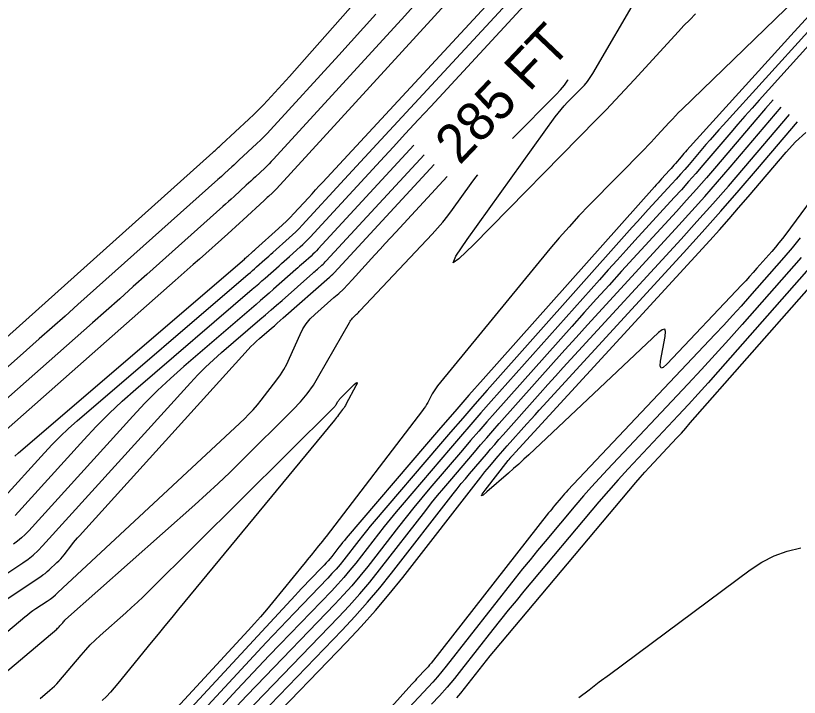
# Model space of a CAD drawing. Extents: x 1768942 to 1774819, y 723037 to 732099.
# Drawn here: x 1771312.2 to 1771433.6, y 725000 to 725105.7 of the extents above; entities that cross this region are included whole.
import ezdxf

# ---------------------------------------------------------------- set-up
doc = ezdxf.new("R2010")
doc.units = 0
doc.layers.add('R_Contour Annot', color=7, linetype='Continuous')
doc.layers.add('R_Contours', color=7, linetype='Continuous')

msp = doc.modelspace()

# ---------------------------------------------------------------- linework, layer by layer
at = {"layer": 'R_Contours'}
for points in [[(1771309.19, 725054.48), (1771342.73, 725084.45), (1771342.84, 725084.55), (1771342.95, 725084.65), (1771343.07, 725084.75), (1771343.18, 725084.86), (1771343.63, 725085.27), (1771343.74, 725085.37), (1771343.85, 725085.47), (1771343.96, 725085.58), (1771344.07, 725085.68), (1771348.33, 725089.65), (1771349.07, 725090.35), (1771349.8, 725091.07), (1771350.51, 725091.8), (1771351.21, 725092.54), (1771354.59, 725096.24), (1771355.38, 725097.11), (1771356.17, 725097.99), (1771356.95, 725098.86), (1771357.73, 725099.74), (1771383.9, 725129.4)], [(1771312.08, 725037.43), (1771312.61, 725037.91), (1771347.62, 725067.96), (1771347.76, 725068.09), (1771347.9, 725068.21), (1771348.05, 725068.33), (1771348.19, 725068.46), (1771348.75, 725068.96), (1771348.9, 725069.09), (1771349.04, 725069.21), (1771349.18, 725069.34), (1771349.32, 725069.46), (1771352.91, 725072.68), (1771353.53, 725073.24), (1771354.12, 725073.81), (1771354.71, 725074.4), (1771355.28, 725075.01), (1771357.53, 725077.45), (1771358.1, 725078.06), (1771358.66, 725078.67), (1771359.22, 725079.28), (1771359.79, 725079.89), (1771394.72, 725117.69)], [(1771384.3, 725113.52), (1771352.58, 725078.84), (1771352.44, 725078.68), (1771352.28, 725078.52), (1771352.13, 725078.37), (1771351.97, 725078.22), (1771351.33, 725077.62), (1771351.17, 725077.47), (1771351.01, 725077.33), (1771350.85, 725077.18), (1771350.69, 725077.03), (1771347.44, 725074.05), (1771346.85, 725073.51), (1771346.25, 725072.96), (1771345.65, 725072.42), (1771345.05, 725071.88), (1771340.64, 725067.94), (1771339.7, 725067.11), (1771338.76, 725066.27), (1771337.82, 725065.44), (1771336.88, 725064.61), (1771306.68, 725037.99)], [(1771309.99, 725030.58), (1771316.65, 725037.92), (1771317.86, 725039.22), (1771319.1, 725040.47), (1771320.39, 725041.68), (1771321.72, 725042.86), (1771348.22, 725065.62), (1771348.54, 725065.89), (1771348.86, 725066.17), (1771349.19, 725066.45), (1771349.5, 725066.73), (1771350.78, 725067.86), (1771351.1, 725068.14), (1771351.42, 725068.42), (1771351.74, 725068.71), (1771352.05, 725068.99), (1771354.56, 725071.23), (1771355.08, 725071.71), (1771355.59, 725072.19), (1771356.08, 725072.69), (1771356.56, 725073.2), (1771363.12, 725080.32), (1771364.38, 725081.67), (1771365.63, 725083.03), (1771366.88, 725084.39), (1771368.14, 725085.75), (1771394.76, 725114.55)], [(1771312.11, 725028.22), (1771322.73, 725039.93), (1771324.66, 725042), (1771326.65, 725044), (1771328.7, 725045.94), (1771330.82, 725047.81), (1771348.83, 725063.27), (1771349.33, 725063.7), (1771349.83, 725064.13), (1771350.33, 725064.57), (1771350.82, 725065.01), (1771352.98, 725066.91), (1771353.39, 725067.27), (1771353.8, 725067.64), (1771354.21, 725068), (1771354.62, 725068.37), (1771356.25, 725069.83), (1771356.65, 725070.2), (1771357.05, 725070.58), (1771357.43, 725070.96), (1771357.81, 725071.36), (1771368.72, 725083.18), (1771370.66, 725085.29), (1771372.6, 725087.39), (1771374.54, 725089.5), (1771376.49, 725091.6), (1771394.8, 725111.41)], [(1771434.68, 725109.88), (1771415.38, 725091.12), (1771414.89, 725090.64), (1771414.4, 725090.14), (1771413.92, 725089.64), (1771413.44, 725089.13), (1771411.56, 725087.07), (1771411.09, 725086.56), (1771410.61, 725086.06), (1771410.13, 725085.55), (1771409.64, 725085.05), (1771401.03, 725076.29), (1771399.45, 725074.64), (1771397.91, 725072.96), (1771396.4, 725071.25), (1771394.94, 725069.51), (1771377.55, 725048.31), (1771377.32, 725048.02), (1771377.11, 725047.71), (1771376.91, 725047.4), (1771376.73, 725047.07), (1771376.02, 725045.75), (1771375.84, 725045.42), (1771375.65, 725045.1), (1771375.44, 725044.79), (1771375.22, 725044.49), (1771360.27, 725024.97), (1771359.99, 725024.6), (1771359.7, 725024.24), (1771359.41, 725023.87), (1771359.12, 725023.51), (1771357.94, 725022.08), (1771357.64, 725021.72), (1771357.35, 725021.36), (1771357.06, 725021.01), (1771356.76, 725020.65), (1771351.96, 725014.72), (1771351.05, 725013.62), (1771350.12, 725012.54), (1771349.18, 725011.47), (1771348.22, 725010.41), (1771332.79, 724993.74)], [(1771417.49, 725105.93), (1771416.6, 725105.03), (1771415.72, 725104.12), (1771414.86, 725103.19), (1771408, 725095.71), (1771406.57, 725094.16), (1771405.12, 725092.62), (1771403.66, 725091.09), (1771402.18, 725089.58), (1771383.09, 725070.15), (1771380.85, 725067.98), (1771379.94, 725067.39), (1771380.36, 725068.39), (1771382.12, 725070.97), (1771395.76, 725089.97), (1771396.21, 725090.57), (1771396.68, 725091.14), (1771397.17, 725091.7), (1771397.69, 725092.24), (1771399.8, 725094.37), (1771400.31, 725094.91), (1771400.78, 725095.48), (1771401.21, 725096.09), (1771401.6, 725096.72), (1771408.8, 725109.07)], [(1771374.25, 725107.61), (1771372.46, 725105.65), (1771352.13, 725083.41), (1771351.79, 725083.05), (1771351.46, 725082.7), (1771351.11, 725082.36), (1771350.76, 725082.03), (1771349.33, 725080.7), (1771348.98, 725080.37), (1771348.62, 725080.04), (1771348.26, 725079.71), (1771347.91, 725079.38), (1771346.02, 725077.65), (1771345.59, 725077.25), (1771345.15, 725076.86), (1771344.71, 725076.46), (1771344.28, 725076.07), (1771332.52, 725065.57), (1771330.41, 725063.69), (1771328.3, 725061.81), (1771326.18, 725059.94), (1771324.07, 725058.07), (1771307.03, 725043.06)], [(1771435.66, 725106.31), (1771432.81, 725103.16), (1771416.16, 725084.81), (1771415.93, 725084.56), (1771415.71, 725084.3), (1771415.49, 725084.05), (1771415.27, 725083.79), (1771414.39, 725082.76), (1771414.17, 725082.5), (1771413.94, 725082.25), (1771413.72, 725081.99), (1771413.49, 725081.74), (1771412.26, 725080.4), (1771411.98, 725080.09), (1771411.7, 725079.78), (1771411.42, 725079.47), (1771411.14, 725079.16), (1771384.62, 725049.36), (1771382.4, 725046.86), (1771380.2, 725044.35), (1771378.01, 725041.82), (1771375.84, 725039.28), (1771363.4, 725024.7), (1771363.11, 725024.35), (1771362.83, 725024.01), (1771362.54, 725023.66), (1771362.27, 725023.31), (1771361.17, 725021.89), (1771360.89, 725021.54), (1771360.6, 725021.2), (1771360.3, 725020.87), (1771360, 725020.54), (1771357.51, 725017.97), (1771357, 725017.43), (1771356.48, 725016.89), (1771355.97, 725016.35), (1771355.46, 725015.8), (1771333.53, 724992.1)], [(1771368, 725105.92), (1771366.09, 725103.79), (1771364.17, 725101.66), (1771362.24, 725099.54), (1771351.67, 725087.98), (1771351.15, 725087.43), (1771350.63, 725086.89), (1771350.09, 725086.36), (1771349.55, 725085.84), (1771346.78, 725083.26), (1771346.51, 725083.01), (1771346.24, 725082.76), (1771345.96, 725082.51), (1771345.69, 725082.26), (1771344.6, 725081.25), (1771344.33, 725081), (1771344.05, 725080.75), (1771343.78, 725080.51), (1771343.5, 725080.26), (1771321.82, 725060.89), (1771319.83, 725059.12), (1771317.84, 725057.35), (1771315.84, 725055.58), (1771313.85, 725053.82), (1771305.85, 725046.77)], [(1771434.9, 725103.18), (1771421.77, 725088.7), (1771421.1, 725087.95), (1771420.43, 725087.2), (1771419.77, 725086.44), (1771419.11, 725085.68), (1771416.51, 725082.62), (1771415.85, 725081.85), (1771415.19, 725081.1), (1771414.52, 725080.35), (1771413.84, 725079.6), (1771410.19, 725075.62), (1771409.36, 725074.7), (1771408.53, 725073.79), (1771407.7, 725072.87), (1771406.87, 725071.95), (1771385.24, 725047.64), (1771383.34, 725045.49), (1771381.44, 725043.32), (1771379.56, 725041.15), (1771377.69, 725038.97), (1771367.72, 725027.28), (1771367.11, 725026.56), (1771366.51, 725025.83), (1771365.92, 725025.09), (1771365.34, 725024.35), (1771363.02, 725021.37), (1771362.43, 725020.64), (1771361.82, 725019.92), (1771361.19, 725019.21), (1771360.55, 725018.52), (1771355.31, 725013.1), (1771354.22, 725011.96), (1771353.14, 725010.82), (1771352.06, 725009.68), (1771350.99, 725008.53), (1771334.28, 724990.46)], [(1771436.99, 725103.19), (1771427.37, 725092.59), (1771426.26, 725091.35), (1771425.15, 725090.1), (1771424.05, 725088.84), (1771422.96, 725087.57), (1771418.63, 725082.48), (1771417.54, 725081.21), (1771416.44, 725079.95), (1771415.32, 725078.7), (1771414.2, 725077.47), (1771408.12, 725070.83), (1771406.74, 725069.32), (1771405.35, 725067.79), (1771403.98, 725066.26), (1771402.61, 725064.73), (1771385.86, 725045.91), (1771384.27, 725044.11), (1771382.68, 725042.3), (1771381.11, 725040.48), (1771379.54, 725038.66), (1771372.04, 725029.86), (1771371.11, 725028.76), (1771370.2, 725027.65), (1771369.29, 725026.53), (1771368.4, 725025.4), (1771364.87, 725020.85), (1771363.97, 725019.73), (1771363.04, 725018.63), (1771362.08, 725017.56), (1771361.1, 725016.51), (1771353.11, 725008.23), (1771351.45, 725006.5), (1771349.8, 725004.76), (1771348.16, 725003.01), (1771346.52, 725001.26), (1771335.02, 724988.82)], [(1771450.24, 725097.21), (1771431.49, 725071.82), (1771430.97, 725071.13), (1771430.43, 725070.45), (1771429.88, 725069.78), (1771429.32, 725069.13), (1771427.03, 725066.53), (1771426.46, 725065.88), (1771425.88, 725065.24), (1771425.29, 725064.6), (1771424.7, 725063.97), (1771413.07, 725051.65), (1771412.51, 725051.15), (1771412.16, 725051.07), (1771412.02, 725051.4), (1771412.09, 725052.15), (1771412.81, 725055.97), (1771412.88, 725056.72), (1771412.73, 725057.07), (1771412.35, 725057.01), (1771411.76, 725056.55), (1771391.67, 725037.64), (1771390.89, 725036.92), (1771390.11, 725036.19), (1771389.31, 725035.48), (1771388.51, 725034.77), (1771385.18, 725031.86), (1771384.6, 725031.38), (1771384.36, 725031.27), (1771384.46, 725031.51), (1771384.9, 725032.12), (1771388.49, 725036.72), (1771388.52, 725036.77), (1771388.56, 725036.82), (1771388.6, 725036.86), (1771388.64, 725036.91), (1771388.8, 725037.1), (1771388.84, 725037.15), (1771388.88, 725037.19), (1771388.92, 725037.24), (1771388.96, 725037.29), (1771389.32, 725037.69), (1771389.39, 725037.77), (1771389.47, 725037.85), (1771389.54, 725037.93), (1771389.61, 725038.01), (1771419.7, 725070.84), (1771421.21, 725072.5), (1771422.7, 725074.18), (1771424.18, 725075.87), (1771425.64, 725077.57), (1771431.56, 725084.51), (1771433.02, 725086.1), (1771434.6, 725087.55)], [(1771389.13, 725086.64), (1771395.93, 725093.47), (1771396.59, 725094.17), (1771397.19, 725094.91), (1771397.75, 725095.69), (1771397.78, 725095.74)], [(1771429.53, 725092.6), (1771428.36, 725091.26), (1771426.87, 725089.52), (1771420.74, 725082.33), (1771419.22, 725080.56), (1771417.68, 725078.8), (1771416.13, 725077.06), (1771414.55, 725075.33), (1771406.05, 725066.05), (1771404.11, 725063.93), (1771402.18, 725061.8), (1771400.26, 725059.66), (1771398.34, 725057.52), (1771386.48, 725044.19), (1771385.2, 725042.74), (1771383.92, 725041.28), (1771382.65, 725039.82), (1771381.39, 725038.35), (1771376.36, 725032.45), (1771375.12, 725030.97), (1771373.88, 725029.47), (1771372.67, 725027.97), (1771371.47, 725026.45), (1771366.72, 725020.33), (1771365.51, 725018.82), (1771364.26, 725017.34), (1771362.97, 725015.9), (1771361.65, 725014.49), (1771349.48, 725001.87), (1771347.96, 725000.29), (1771346.45, 724998.7)], [(1771340.45, 724987.33), (1771362.75, 725010.45), (1771364.75, 725012.59), (1771366.7, 725014.77), (1771368.59, 725017.01), (1771370.41, 725019.29), (1771379.98, 725031.58), (1771380.6, 725032.37), (1771381.22, 725033.15), (1771381.86, 725033.92), (1771382.5, 725034.68), (1771385.1, 725037.72), (1771385.75, 725038.48), (1771386.4, 725039.24), (1771387.06, 725039.99), (1771387.72, 725040.74), (1771393.46, 725047.18), (1771394.64, 725048.51), (1771395.83, 725049.82), (1771397.02, 725051.13), (1771398.21, 725052.44), (1771415.26, 725071.05), (1771417.73, 725073.77), (1771420.17, 725076.51), (1771422.59, 725079.27), (1771424.98, 725082.05), (1771432.05, 725090.36)], [(1771344.96, 724994.6), (1771362.2, 725012.47), (1771363.86, 725014.24), (1771365.48, 725016.06), (1771367.05, 725017.91), (1771368.56, 725019.81), (1771375.72, 725029.01), (1771376.63, 725030.17), (1771377.55, 725031.31), (1771378.49, 725032.44), (1771379.43, 725033.56), (1771383.25, 725038.03), (1771384.2, 725039.15), (1771385.16, 725040.26), (1771386.13, 725041.36), (1771387.1, 725042.46), (1771395.53, 725051.93), (1771397.27, 725053.87), (1771399.01, 725055.81), (1771400.75, 725057.74), (1771402.51, 725059.66), (1771414.91, 725073.19), (1771416.93, 725075.41), (1771418.93, 725077.65), (1771420.91, 725079.91), (1771422.86, 725082.19), (1771430.78, 725091.49)], [(1771350.38, 724995.05), (1771363.44, 725008.59), (1771365.72, 725011.01), (1771367.92, 725013.48), (1771370.06, 725016.02), (1771372.14, 725018.61), (1771384.23, 725034.15), (1771384.56, 725034.57), (1771384.89, 725034.98), (1771385.23, 725035.39), (1771385.57, 725035.8), (1771386.95, 725037.41), (1771387.3, 725037.81), (1771387.64, 725038.22), (1771387.99, 725038.61), (1771388.34, 725039.01), (1771391.39, 725042.43), (1771392.02, 725043.14), (1771392.65, 725043.84), (1771393.28, 725044.53), (1771393.91, 725045.23), (1771415.62, 725068.91), (1771418.53, 725072.12), (1771421.42, 725075.36), (1771424.28, 725078.62), (1771427.1, 725081.91), (1771433.33, 725089.22)], [(1771373.89, 725085.6), (1771359.06, 725069.52), (1771358.79, 725069.24), (1771358.51, 725068.96), (1771358.23, 725068.69), (1771357.94, 725068.42), (1771356.77, 725067.37), (1771356.47, 725067.11), (1771356.18, 725066.85), (1771355.89, 725066.59), (1771355.59, 725066.33), (1771352.14, 725063.28), (1771351.47, 725062.69), (1771350.79, 725062.1), (1771350.11, 725061.51), (1771349.43, 725060.92), (1771338.22, 725051.3), (1771336.15, 725049.47), (1771334.15, 725047.58), (1771332.2, 725045.62), (1771330.32, 725043.61), (1771314.23, 725025.86), (1771313.68, 725025.29), (1771313.1, 725024.75), (1771312.48, 725024.25), (1771311.83, 725023.79)], [(1771309.91, 725018.62), (1771313.3, 725020.87), (1771314.12, 725021.46), (1771314.91, 725022.09), (1771315.65, 725022.77), (1771316.35, 725023.5), (1771339.27, 725048.78), (1771340.42, 725050.01), (1771341.6, 725051.2), (1771342.83, 725052.35), (1771344.09, 725053.47), (1771350.03, 725058.57), (1771350.89, 725059.32), (1771351.75, 725060.06), (1771352.61, 725060.81), (1771353.46, 725061.55), (1771358.21, 725065.75), (1771358.38, 725065.9), (1771358.56, 725066.06), (1771358.74, 725066.22), (1771358.92, 725066.38), (1771359.63, 725067.01), (1771359.8, 725067.17), (1771359.97, 725067.34), (1771360.14, 725067.51), (1771360.31, 725067.68), (1771375.46, 725084.11)], [(1771308.94, 725014.05), (1771316.07, 725018.77), (1771316.41, 725019.01), (1771316.74, 725019.25), (1771317.06, 725019.52), (1771317.37, 725019.79), (1771318.58, 725020.92), (1771318.88, 725021.21), (1771319.16, 725021.51), (1771319.43, 725021.82), (1771319.69, 725022.14), (1771320.87, 725023.67), (1771321.15, 725024.03), (1771321.44, 725024.39), (1771321.74, 725024.74), (1771322.05, 725025.08), (1771348.22, 725053.95), (1771348.63, 725054.39), (1771349.06, 725054.82), (1771349.5, 725055.24), (1771349.95, 725055.64), (1771351.8, 725057.22), (1771352.26, 725057.62), (1771352.72, 725058.02), (1771353.17, 725058.42), (1771353.63, 725058.82), (1771360.82, 725065.16), (1771360.88, 725065.22), (1771360.94, 725065.27), (1771361.01, 725065.33), (1771361.07, 725065.38), (1771361.32, 725065.61), (1771361.38, 725065.66), (1771361.44, 725065.72), (1771361.5, 725065.78), (1771361.55, 725065.84), (1771377.03, 725082.61)], [(1771307.95, 725001.68), (1771318.56, 725010.63), (1771318.68, 725010.74), (1771318.8, 725010.85), (1771318.92, 725010.98), (1771319.03, 725011.1), (1771319.47, 725011.61), (1771319.58, 725011.74), (1771319.69, 725011.86), (1771319.81, 725011.98), (1771319.93, 725012.09), (1771339.95, 725029.88), (1771341.77, 725031.52), (1771343.57, 725033.19), (1771345.34, 725034.88), (1771347.09, 725036.59), (1771355.17, 725044.62), (1771356.31, 725045.82), (1771357.35, 725047.09), (1771358.31, 725048.43), (1771359.17, 725049.84), (1771363.89, 725058.14), (1771364, 725058.32), (1771364.12, 725058.49), (1771364.25, 725058.65), (1771364.39, 725058.8), (1771364.98, 725059.39), (1771365.13, 725059.54), (1771365.27, 725059.69), (1771365.42, 725059.84), (1771365.56, 725059.99), (1771376.71, 725071.83), (1771377.55, 725072.74), (1771378.35, 725073.68), (1771379.12, 725074.64), (1771379.85, 725075.64), (1771382.74, 725079.66), (1771383.48, 725080.65), (1771383.76, 725080.99)], [(1771308.96, 725008.62), (1771313.6, 725012.52), (1771314.01, 725012.85), (1771314.43, 725013.18), (1771314.86, 725013.49), (1771315.3, 725013.79), (1771317.07, 725014.96), (1771317.51, 725015.26), (1771317.93, 725015.58), (1771318.34, 725015.92), (1771318.73, 725016.27), (1771347.61, 725043.22), (1771348.31, 725043.91), (1771348.98, 725044.61), (1771349.63, 725045.35), (1771350.24, 725046.11), (1771352.63, 725049.22), (1771353.21, 725050.01), (1771353.73, 725050.83), (1771354.2, 725051.69), (1771354.62, 725052.57), (1771356.24, 725056.25), (1771356.68, 725057.12), (1771357.21, 725057.93), (1771357.82, 725058.68), (1771358.52, 725059.36), (1771361.5, 725061.97), (1771362.23, 725062.63), (1771362.95, 725063.31), (1771363.64, 725064.02), (1771364.31, 725064.74), (1771367.82, 725068.6), (1771368.63, 725069.49), (1771369.44, 725070.37), (1771370.25, 725071.25), (1771371.06, 725072.14), (1771379.01, 725080.73)], [(1771380.54, 724999.99), (1771381.13, 725000.69), (1771381.7, 725001.41), (1771383.97, 725004.3), (1771384.54, 725005.02), (1771385.11, 725005.73), (1771385.69, 725006.45), (1771386.28, 725007.15), (1771408.27, 725033.33), (1771408.95, 725034.13), (1771409.63, 725034.91), (1771410.33, 725035.68), (1771411.04, 725036.44), (1771413.9, 725039.47), (1771414.61, 725040.23), (1771415.31, 725041), (1771416.01, 725041.77), (1771416.7, 725042.55), (1771443.15, 725072.64)], [(1771433.74, 725071.23), (1771432.47, 725069.69), (1771431.17, 725068.18), (1771425.89, 725062.17), (1771424.56, 725060.67), (1771423.22, 725059.19), (1771421.87, 725057.72), (1771420.5, 725056.26), (1771397.72, 725032.12), (1771397.46, 725031.84), (1771397.2, 725031.55), (1771396.95, 725031.27), (1771396.7, 725030.98), (1771395.71, 725029.8), (1771395.47, 725029.51), (1771395.23, 725029.21), (1771394.98, 725028.91), (1771394.75, 725028.61), (1771376.54, 725005.36), (1771376.3, 725005.07), (1771376.07, 725004.79), (1771375.82, 725004.51), (1771375.57, 725004.24), (1771374.55, 725003.16), (1771374.3, 725002.89), (1771374.05, 725002.62), (1771373.8, 725002.34), (1771373.55, 725002.07), (1771351.36, 724977.34)], [(1771438.5, 725070.41), (1771420.97, 725050.46), (1771419.46, 725048.76), (1771417.94, 725047.07), (1771416.4, 725045.4), (1771414.84, 725043.73), (1771408.6, 725037.12), (1771407.05, 725035.45), (1771405.52, 725033.76), (1771404.02, 725032.05), (1771402.54, 725030.32), (1771390.92, 725016.49), (1771389.71, 725015.02), (1771388.5, 725013.55), (1771387.3, 725012.06), (1771386.12, 725010.57), (1771381.27, 725004.37), (1771380.15, 725002.98), (1771379.01, 725001.62), (1771377.83, 725000.28), (1771376.63, 724998.98)], [(1771433.86, 725068.17), (1771424.75, 725057.81), (1771422.67, 725055.47), (1771420.57, 725053.14), (1771418.45, 725050.84), (1771416.31, 725048.55), (1771403.86, 725035.37), (1771402.61, 725034.02), (1771401.37, 725032.65), (1771400.16, 725031.26), (1771398.96, 725029.86), (1771394.22, 725024.21), (1771393.04, 725022.8), (1771391.87, 725021.37), (1771390.72, 725019.94), (1771389.57, 725018.49), (1771378.9, 725004.87), (1771378.23, 725004.03), (1771377.54, 725003.2), (1771376.83, 725002.4), (1771376.1, 725001.61), (1771373.15, 724998.48)], [(1771315.97, 724999.85), (1771317.48, 725001.13), (1771317.85, 725001.45), (1771318.21, 725001.79), (1771318.55, 725002.15), (1771318.88, 725002.52), (1771322.33, 725006.6), (1771323.03, 725007.4), (1771323.75, 725008.17), (1771324.5, 725008.91), (1771325.28, 725009.62), (1771329.23, 725013.13), (1771330.14, 725013.95), (1771331.04, 725014.79), (1771331.94, 725015.64), (1771332.82, 725016.5), (1771361.53, 725045), (1771361.62, 725045.09), (1771361.7, 725045.19), (1771361.78, 725045.3), (1771361.85, 725045.41), (1771362.11, 725045.87), (1771362.18, 725045.99), (1771362.25, 725046.09), (1771362.33, 725046.19), (1771362.42, 725046.29), (1771364.62, 725048.5), (1771364.93, 725048.78), (1771365.08, 725048.85), (1771365.07, 725048.69), (1771364.89, 725048.3), (1771363.4, 725045.5), (1771363.28, 725045.27), (1771363.14, 725045.05), (1771363, 725044.83), (1771362.84, 725044.62), (1771362.21, 725043.79), (1771362.05, 725043.58), (1771361.88, 725043.38), (1771361.72, 725043.17), (1771361.56, 725042.97), (1771337.42, 725013.71), (1771336.36, 725012.42), (1771335.3, 725011.14), (1771334.25, 725009.85), (1771333.2, 725008.56), (1771328.03, 725002.19), (1771327.46, 725001.51), (1771326.86, 725000.84), (1771326.24, 725000.19), (1771325.6, 724999.57)], [(1771399.43, 725000.02), (1771401.01, 725001.22), (1771402.59, 725002.42), (1771404.18, 725003.6), (1771425.99, 725019.8), (1771427.8, 725020.99), (1771429.7, 725021.96), (1771431.71, 725022.7), (1771433.81, 725023.21)]]:
    msp.add_lwpolyline(points, dxfattribs=at)

# ---------------------------------------------------------------- texts
at = {"layer": 'R_Contour Annot'}
msp.add_text('285 FT', height=6, rotation=46.4509, dxfattribs=at).set_placement((1771380.98, 725082.41))

doc.saveas('drawing.dxf')
